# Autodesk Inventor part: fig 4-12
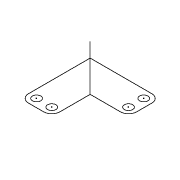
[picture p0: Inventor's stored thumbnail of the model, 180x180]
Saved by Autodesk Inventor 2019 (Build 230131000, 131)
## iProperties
Created: 2005-02
Part Number: fig 4-12
Document SubType Name: Modeling
Designer: CADCIM
Manufacturer: Standard
Standards Organization: Custom
Density: 1 g/cm^3
Material: Generic
Appearance: Default
Author: CADCIM
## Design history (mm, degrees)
sketch "Sketch1"
  geometry: L1 (5.141, 24.979)-(-32.827, 24.979); L2 (-32.827, 24.979)-(-32.827, -12.989); L3 (-27.827, -17.989)-(-18.492, -17.989); L4 (-13.492, -12.989)-(-13.492, 5.644); L5 (-13.492, 5.644)-(5.141, 5.644); L6 (10.141, 10.644)-(10.141, 19.979); L7 (-13.492, 5.644)-(-41.603, 33.755); C1 r 2.58 at (-27.827, -12.989); C2 r 2.58 at (-18.492, -12.989); C3 r 2.58 at (5.141, 10.644); C4 r 2.58 at (5.141, 19.979); A1 r 5 centre (-27.827, -12.989) between (-32.827, -12.989) and (-27.827, -17.989); A2 r 5 centre (-18.492, -12.989) between (-18.492, -17.989) and (-13.492, -12.989); A3 r 5 centre (5.141, 10.644) between (5.141, 5.644) and (10.141, 10.644); A4 r 5 centre (5.141, 19.979) between (10.141, 19.979) and (5.141, 24.979)
  constraints: 14 end point, 8 centre point, 8 point on circle, 8 tangent, 4 equal radius, 4 parallel, 3 perpendicular, 2 coincident, 1 horizontal
